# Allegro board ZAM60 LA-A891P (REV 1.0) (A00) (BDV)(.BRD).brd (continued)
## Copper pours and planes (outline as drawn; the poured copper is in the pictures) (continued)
GND on IN2 (solid shape): 11.19,11.92 11.19,11.45 10.69,10.96 9.66,10.96 9.52,11.1 9.52,11.81 9.76,12.05 11.06,12.05
GND on IN2 (solid shape): 17.78,13.86 17.78,12.86 17.6,12.69 16.6,12.69 16.35,12.93 16.35,13.76 16.55,13.96 17.68,13.96
GND on IN2 (solid shape): 16.43,18.26 16.43,17.02 16.18,16.78 15.1,16.78 14.91,16.97 14.91,18.24 15.02,18.35 16.33,18.35
GND on IN2 (solid shape): 52.14,15.46 52.14,12.05 51.88,11.79 47.43,11.79 47.1,12.12 47.1,15.48 47.54,15.92 51.68,15.92
GND on IN2 (solid shape): 17.3,15.89 17.3,14.81 17.13,14.64 16.09,14.64 15.61,15.13 15.61,15.85 15.94,16.18 17.02,16.18
GND on IN2 (solid shape): 103.12,57.51 103.12,47.21 102.79,46.88 100.4,46.88 100.26,47.01 100.26,57.44 100.58,57.76 102.87,57.76
GND on IN2 (solid shape): 295.11,70.46 295.37,70.02 295.85,69.84 300.25,69.84 300.25,69.85 301.15,69.85 301.32,69.77 301.4,69.6 301.4,63.45 301.32,63.28 301.15,63.2 300.25,63.2 300.25,63.21 296.5,63.21 296.5,63.2 292.46,63.2 291.62,63.69 291,62.95 291,61.76 287.78,61.76 287.33,62.2 287.33,62.9 287.72,63.28 287.72,64.3 291.27,67.86 291.27,69.63 291.59,69.95 294.07,69.95 294.58,70.46
GND on IN2 (solid shape): outline of 89 points within 70.81,70.97 77.85,81.13
GND on IN2 (solid shape): 233.25,109.24 233.75,109.05 233.99,108.57 234.02,108.34 235.59,108.34 235.59,98.3 235.62,98.09 235.71,97.9 235.71,96.75 235.26,96.3 231.57,96.3 230.69,97.18 230.69,100.81 230.25,101.26 226.5,101.26 225.87,100.62 225.87,98.21 225.23,97.57 222.06,97.57 221.68,97.95 221.68,101.19 222.35,101.19 223.41,100.99 223.21,102.05 223.21,108.29 224.94,108.29 224.96,108.54 225.19,109.04 225.7,109.24
GND on IN2 (solid shape): 253.09,107.5 257.35,103.24 261.61,107.5 261.61,108.62 263.89,108.62 263.89,100.56 263.5,100.23 263.4,99.73 261.56,99.73 260.22,101.07 257.36,101.07 255.65,99.35 255.65,97.19 255.08,96.62 250.38,96.62 250.01,96.99 250.01,108.34 251.58,108.34 251.61,108.57 251.85,109.05 252.34,109.24 253.09,109.24
GND on IN2 (solid shape): outline of 206 points within 283.79,78.69 303.15,94.03
GND on IN2 (solid shape): outline of 109 points within 0.25,0.25 304.5,50.58
GND on IN2 (solid shape): outline of 541 points within 33.97,27.99 77.49,109.25
GND on IN2 (solid shape): 100.54,100.85 107.7,93.69 114.86,100.85 114.86,107.74 125.7,107.74 126.59,108.11 127.03,109.17 127.2,109.24 177.7,109.24 177.87,109.17 178.31,108.11 179.2,107.74 188.54,107.74 188.54,100.85 195.7,93.69 202.86,100.85 202.86,109.24 204.7,109.24 205.21,109.04 205.44,108.54 205.46,108.29 207.19,108.29 207.19,102.05 206.99,100.99 208.05,101.19 208.79,101.19 208.79,97.95 208.4,97.57 202.62,97.57 194.02,93.38 188.04,100.85 188.04,102.95 187.58,103.42 183.7,103.42 182.24,104.88 182.24,106.67 181.67,107.24 179.2,107.24 178.05,107.67 177.46,108.74 127.44,108.74 126.85,107.67 125.7,107.24 121.61,107.24 121.16,106.78 121.16,104.81 119.76,103.42 115.88,103.42 115.36,102.89 115.36,100.85 108.91,93.28 100.42,98.46 95.12,98.46 93.34,96.68 92.2,96.68 91.91,96.98 91.91,108.34 93.48,108.34 93.51,108.57 93.75,109.05 94.24,109.24 100.54,109.24
GND on IN2 (solid shape): outline of 11195 points within 71.12,10.13 227.39,27.52
GND on IN3 (solid shape): 52.58,15.79 52.58,12.04 52.32,11.79 47.57,11.79 47.32,12.04 47.32,15.16 48.19,16.04 52.32,16.04
GND on IN3 (solid shape): 103.12,57.51 103.12,47.36 102.79,47.03 100.37,47.03 100.26,47.13 100.26,57.38 100.64,57.76 102.87,57.76
GND on IN3 (solid shape): 295.11,70.46 295.37,70.02 295.85,69.84 300.33,69.84 300.33,69.85 301.15,69.85 301.32,69.77 301.4,69.6 301.4,63.45 301.32,63.28 301.15,63.2 300.33,63.2 300.33,63.21 296.77,63.21 296.77,63.2 292.46,63.2 291.62,63.69 291,62.95 291,61.76 287.78,61.76 287.33,62.2 287.33,62.9 287.72,63.28 287.72,64.3 291.27,67.86 291.27,69.63 291.59,69.95 294.07,69.95 294.58,70.46
GND on IN3 (solid shape): outline of 89 points within 71.88,71.06 77.58,81.11
GND on IN3 (solid shape): 233.25,109.24 233.75,109.05 233.99,108.57 234.02,108.34 235.59,108.34 235.59,98.3 235.62,98.09 235.71,97.9 235.71,96.75 235.26,96.3 230.88,96.3 230.69,96.49 230.69,100.81 230.25,101.26 226.5,101.26 225.87,100.62 225.87,98.21 225.23,97.57 222.06,97.57 221.68,97.95 221.68,101.19 222.35,101.19 223.41,100.99 223.21,102.05 223.21,108.29 224.94,108.29 224.96,108.54 225.19,109.04 225.7,109.24
GND on IN3 (solid shape): 253.09,107.5 257.35,103.24 261.61,107.5 261.61,108.62 263.89,108.62 263.89,100.56 263.5,100.23 263.4,99.73 261.56,99.73 260.22,101.07 257.36,101.07 255.65,99.35 255.65,97.19 255.08,96.62 250.38,96.62 250.01,96.99 250.01,108.34 251.58,108.34 251.61,108.57 251.85,109.05 252.34,109.24 253.09,109.24
GND on IN3 (solid shape): outline of 206 points within 283.79,78.69 303.15,94.03
GND on IN3 (solid shape): outline of 542 points within 33.97,27.99 77.49,109.25
GND on IN3 (solid shape): 100.54,100.85 107.7,93.69 114.86,100.85 114.86,107.74 125.7,107.74 126.59,108.11 127.03,109.17 127.2,109.24 177.7,109.24 177.87,109.17 178.31,108.11 179.2,107.74 188.54,107.74 188.54,100.85 195.7,93.69 202.86,100.85 202.86,109.24 204.7,109.24 205.21,109.04 205.44,108.54 205.46,108.29 207.19,108.29 207.19,102.05 206.99,100.99 208.05,101.19 208.79,101.19 208.79,97.95 208.4,97.57 202.62,97.57 194.02,93.38 188.04,100.85 188.04,102.95 187.58,103.42 183.7,103.42 182.24,104.88 182.24,106.67 181.67,107.24 179.2,107.24 178.05,107.67 177.46,108.74 127.44,108.74 126.85,107.67 125.7,107.24 121.6,107.24 121.16,106.79 121.16,104.81 119.76,103.42 115.88,103.42 115.36,102.89 115.36,100.85 108.91,93.28 100.42,98.46 95.12,98.46 93.34,96.68 92.2,96.68 91.91,96.98 91.91,108.34 93.48,108.34 93.51,108.57 93.75,109.05 94.24,109.24 100.54,109.24
GND on IN3 (solid shape): outline of 11893 points within 0.25,0.25 304.5,51.6
GND on IN4 (solid shape): 52.58,15.79 52.58,12.04 52.32,11.79 47.48,11.79 47.29,11.98 47.29,14.71 48.63,16.04 52.32,16.04
GND on IN4 (solid shape): 75.79,74.78 75.79,71.64 75.54,71.39 74.13,71.39 73.94,71.58 73.94,74.69 74.15,74.9 75.66,74.9
GND on IN4 (solid shape): 103.69,57.57 103.69,52.17 103.38,51.85 100.58,51.85 100.26,52.17 100.26,57.25 101.03,58.01 103.25,58.01
GND on IN4 (solid shape): 295.11,70.46 295.37,70.02 295.85,69.84 299.55,69.84 299.55,69.85 301.15,69.85 301.32,69.77 301.4,69.6 301.4,63.45 301.32,63.28 301.15,63.2 299.55,63.2 299.55,63.21 296.41,63.21 296.41,63.2 292.46,63.2 291.62,63.69 291,62.95 291,61.76 287.78,61.76 287.33,62.2 287.33,62.9 287.72,63.28 287.72,64.3 291.27,67.86 291.27,69.63 291.59,69.95 294.07,69.95 294.58,70.46
GND on IN4 (solid shape): 233.25,109.24 233.75,109.05 233.99,108.57 234.02,108.34 235.59,108.34 235.59,98.3 235.62,98.09 235.71,97.9 235.71,96.94 235.39,96.62 234.69,96.62 233.17,98.15 230.88,98.15 230.69,98.34 230.69,100.81 230.25,101.26 226.5,101.26 225.87,100.62 225.87,98.34 225.61,98.08 223.2,98.08 222.69,97.57 222.06,97.57 221.68,97.95 221.68,101.19 222.35,101.19 223.41,100.99 223.21,102.05 223.21,108.29 224.94,108.29 224.96,108.54 225.19,109.04 225.7,109.24
GND on IN4 (solid shape): 253.09,107.5 257.35,103.24 261.61,107.5 261.61,108.62 263.89,108.62 263.89,100.56 263.5,100.23 263.4,99.73 261.56,99.73 260.22,101.07 257.36,101.07 255.65,99.35 255.65,97.19 255.08,96.62 250.38,96.62 250.01,96.99 250.01,108.34 251.58,108.34 251.61,108.57 251.85,109.05 252.34,109.24 253.09,109.24
GND on IN4 (solid shape): outline of 206 points within 283.79,78.69 303.15,94.03
GND on IN4 (solid shape): outline of 84 points within 33.97,27.99 77.49,109.25
GND on IN4 (solid shape): 100.54,100.85 107.7,93.69 114.86,100.85 114.86,107.74 125.7,107.74 126.59,108.11 127.03,109.17 127.2,109.24 177.7,109.24 177.87,109.17 178.31,108.11 179.2,107.74 188.54,107.74 188.54,100.85 195.7,93.69 202.86,100.85 202.86,109.24 204.7,109.24 205.21,109.04 205.44,108.54 205.46,108.29 207.19,108.29 207.19,102.05 206.99,100.99 208.05,101.19 208.79,101.19 208.79,97.95 208.4,97.57 202.62,97.57 194.02,93.38 188.04,100.85 188.04,102.95 187.58,103.42 183.7,103.42 182.24,104.88 182.24,106.65 181.66,107.24 179.2,107.24 178.05,107.67 177.46,108.74 127.44,108.74 126.85,107.67 125.7,107.24 121.61,107.24 121.16,106.78 121.16,104.81 119.76,103.42 115.88,103.42 115.36,102.89 115.36,100.85 108.91,93.28 100.42,98.46 95.12,98.46 94.04,97.38 94.04,88.68 93.98,88.62 90.48,88.62 90.48,89.83 92.39,91.73 92.39,96.53 92.2,96.72 92.17,96.72 91.91,96.98 91.91,108.34 93.48,108.34 93.51,108.57 93.75,109.05 94.24,109.24 100.54,109.24
GND on IN4 (solid shape): outline of 1654 points within 0.25,0.25 304.5,51.6
GND on IN4 (solid shape): outline of 2939 points within 117.52,55.54 154.56,70.08
GND on GND1: outline of 584 points within 0.25,0.25 304.5,109.25
GND on VCC: 65.26,79.44 65.16,79.6 63.93,81.28 62.61,82.89 62.6,83.01 62.7,83.06 63.06,83.26 62.99,83.66 62.96,83.73 62.99,83.8 62.74,84.4 62.48,83.8 62.51,83.73 62.48,83.66 62.41,83.55 62.38,83.42 62.31,83.33 62.2,83.36 58.79,86.67 54.96,89.49 54.12,89.87 53.2,90 50.27,90 50.27,100.58 51.5,100.58 53.1,101.25 53.77,102.85 53.77,108.23 71.3,108.23 71.36,108.17 71.36,85.42 65.38,79.44
GND on VCC: 176.56,9.32 175.17,10.71 143.97,10.71 142.7,9.44 113.09,9.44 113.09,47.16 119.53,47.16 120.19,47.82 120.19,53.6 121.5,54.91 124.87,54.91 128.93,58.97 134.44,58.97 135.07,58.34 159.2,58.34 160.32,57.22 160.32,53.66 164.14,49.78 164.14,48.38 165.12,47.41 168.74,47.41 170.01,46.14 177.5,46.14 178.14,45.5 190.71,45.5 191.34,44.87 198.39,44.87 222.44,20.89 222.42,10.69 221.05,9.32
GND on GND2: outline of 213 points within 0.25,0.25 304.5,109.25
GND on GND3: outline of 212 points within 0.25,0.25 304.5,109.25
GNDA on TOP (solid shape): 2.08,15.34 0.76,15.34 0.76,13.69 0.26,13.69 0.26,15.84 2.08,15.84
GNDA on TOP (solid shape): 1.44,28.49 33.46,28.49 33.46,27.99 1.4,27.99 1,27.99 0.83,27.92 0.76,27.75 0.76,24.66 1.44,24.66 1.44,24.15 0.25,24.15 0.25,27.75 0.47,28.28 1,28.5 1.44,28.5
GNDA on BOTTOM (solid shape): 2.08,15.34 0.76,15.34 0.76,13.69 0.26,13.69 0.26,15.84 2.08,15.84
GNDA on BOTTOM (solid shape): 1.31,28.49 33.46,28.49 33.46,27.99 0.99,27.99 0.83,27.92 0.76,27.76 0.76,24.66 1.63,24.66 1.63,24.16 0.26,24.16 0.26,27.55 0.25,27.55 0.25,27.75 0.47,28.28 1,28.5 1.31,28.5
GNDA on BOTTOM (solid shape): outline of 101 points within 25.65,15.6 30.41,21.69
GNDA on IN1 (solid shape): 2.08,15.34 0.76,15.34 0.76,13.69 0.26,13.69 0.26,15.84 2.08,15.84
GNDA on IN1 (solid shape): 1.3,28.49 33.46,28.49 33.46,27.99 0.99,27.99 0.83,27.92 0.76,27.76 0.76,24.66 1.63,24.66 1.63,24.16 0.26,24.16 0.26,27.45 0.25,27.45 0.25,27.75 0.47,28.28 1,28.5 1.3,28.5
GNDA on IN2 (solid shape): 2.08,15.34 0.76,15.34 0.76,13.69 0.26,13.69 0.26,15.84 2.08,15.84
GNDA on IN2 (solid shape): 1.25,28.49 33.46,28.49 33.46,27.99 0.99,27.99 0.83,27.92 0.76,27.76 0.76,24.66 1.63,24.66 1.63,24.16 0.26,24.16 0.26,27.48 0.25,27.48 0.25,27.75 0.47,28.28 1,28.5 1.25,28.5
GNDA on IN3 (solid shape): 2.08,15.34 0.76,15.34 0.76,13.69 0.26,13.69 0.26,15.84 2.08,15.84
GNDA on IN3 (solid shape): 1.31,28.49 33.46,28.49 33.46,27.99 0.99,27.99 0.83,27.92 0.76,27.76 0.76,24.66 1.63,24.66 1.63,24.16 0.26,24.16 0.26,27.55 0.25,27.55 0.25,27.75 0.47,28.28 1,28.5 1.31,28.5
GNDA on IN4 (solid shape): 2.08,15.34 0.76,15.34 0.76,13.69 0.26,13.69 0.26,15.84 2.08,15.84
GNDA on IN4 (solid shape): 1.31,28.49 33.46,28.49 33.46,27.99 0.99,27.99 0.83,27.92 0.76,27.76 0.76,24.66 1.63,24.66 1.63,24.16 0.26,24.16 0.26,27.55 0.25,27.55 0.25,27.75 0.47,28.28 1,28.5 1.31,28.5
GNDA on GND1: 27.98,10.96 26.33,12.61 10.14,12.61 9.06,13.69 0.26,13.69 0.26,15.84 12.45,15.84 13.19,16.47 12.71,17.31 12.71,22.69 13.19,23.53 12.45,24.15 0.26,24.15 0.26,27.47 0.25,27.47 0.25,27.75 0.47,28.28 1,28.5 1.31,28.5 1.31,28.49 33.46,28.49 33.46,22.49 33.02,22.05 33.02,20.27 32.91,20.17 31.07,20.17 30.67,19.76 30.67,15.36 31.07,14.96 32.15,14.96 32.19,14.92 32.19,13.6 31.62,13.03 31.62,12.53 31.11,12.02 31.11,11.19 30.88,10.96
GNDA on VCC: 27.98,10.96 26.33,12.61 10.14,12.61 9.06,13.69 1.27,13.69 1.27,14.83 12.45,14.83 14.08,15.91 13.72,17.83 13.72,22.17 14.08,24.09 12.45,25.17 1.27,25.17 1.27,27.48 33.46,27.48 33.46,22.49 33.02,22.05 33.02,20.27 32.91,20.17 31.07,20.17 30.67,19.76 30.67,15.36 31.07,14.96 32.15,14.96 32.19,14.92 32.19,13.6 31.62,13.03 31.62,12.53 31.11,12.02 31.11,11.19 30.88,10.96
GNDA on GND2: 27.98,10.96 26.33,12.61 10.14,12.61 9.06,13.69 0.26,13.69 0.26,15.84 12.45,15.84 13.19,16.47 12.71,17.31 12.71,22.69 13.19,23.53 12.45,24.15 0.26,24.15 0.26,27.09 0.25,27.09 0.25,27.75 0.47,28.28 1,28.5 1.43,28.5 1.43,28.49 33.46,28.49 33.46,22.49 33.02,22.05 33.02,20.27 32.91,20.17 31.07,20.17 30.67,19.76 30.67,15.36 31.07,14.96 32.15,14.96 32.19,14.92 32.19,13.6 31.62,13.03 31.62,12.53 31.11,12.02 31.11,11.19 30.88,10.96
GNDA on GND3: 27.98,10.96 26.33,12.61 10.14,12.61 9.06,13.69 0.26,13.69 0.26,15.84 12.45,15.84 13.19,16.47 12.71,17.31 12.71,22.69 13.19,23.53 12.45,24.15 0.26,24.15 0.26,27.27 0.25,27.27 0.25,27.75 0.47,28.28 1,28.5 1.08,28.49 33.46,28.49 33.46,22.49 33.02,22.05 33.02,20.27 32.91,20.17 31.07,20.17 30.67,19.76 30.67,15.36 31.07,14.96 32.15,14.96 32.19,14.92 32.19,13.6 31.62,13.03 31.62,12.53 31.11,12.02 31.11,11.19 30.88,10.96
GNDA_CHG on TOP (solid shape): 81.79,84.68 81.91,84.56 82.48,84.56 82.48,83.98 82.23,83.73 82.23,82.78 82.36,82.65 82.36,82.02 81.58,82.02 81.07,81.51 77.78,81.51 77.53,81.25 77.53,80.68 77.4,80.56 76.77,80.56 76.77,81.13 76.26,81.13 76.26,80.56 76.01,80.56 76.01,81.38 76.34,81.71 76.34,82.16 77.14,82.95 77.14,85.14 81.79,85.14
VDD_1.35V on BOTTOM (solid shape): 66.47,9.82 66.47,9.7 65.77,9 64.88,9 64.75,9.13 64.75,9.38 64.88,9.51 65.33,9.51 65.71,9.89 66.4,9.89
+BL_PWR_SRC on TOP (solid shape): 108.6,89.55 108.51,89.12 108.92,88.94 110.37,87.49 110.67,87.49 112.39,85.76 112.65,85.76 112.96,85.45 112.96,84.37 112.77,84.18 108.96,84.18 108.07,85.06 107.63,85.06 107.63,87.29 106.55,88.37 106.55,89.66 106.71,89.83 108.33,89.83
+BL_PWR_SRC on BOTTOM (solid shape): 108.09,90.87 108.09,89.6 108.33,89.36 108.33,89.03 108.2,88.9 106.74,88.9 106.61,89.03 106.61,89.36 106.82,89.56 106.82,90.87 106.89,90.94 108.01,90.94
+DC_IN on BOTTOM (solid shape): outline of 232 points within 62.89,93.33 69.05,106.45
+DC_IN_SS on TOP (solid shape): 60.82,99.99 60.82,96.18 64.4,92.61 64.4,90.72 63.98,90.29 59.33,90.29 58.67,90.95 58.67,94.37 57.21,95.83 57.21,99.86 57.53,100.18 60.63,100.18
+DC_IN_SS on BOTTOM (solid shape): 64.16,95 64.16,92.81 64.41,92.56 64.41,92.13 64.62,91.92 64.78,91.92 64.89,91.81 64.89,91.03 64.82,90.96 62.48,90.96 62.25,90.72 61.47,90.72 61.17,91.02 61.17,95.01 61.37,95.21 63.94,95.21
+DCIN on BOTTOM (solid shape): 77.79,88.91 77.79,88.08 77.47,87.76 77.47,85.23 78.01,84.68 78.01,84.35 77.91,84.25 77.2,84.25 76.64,84.81 73.39,84.81 73.02,85.18 73.02,87.07 73.33,87.38 74.74,87.38 75.03,87.67 75.21,87.67 75.43,87.89 75.43,88.07 76.37,89.01 77.7,89.01
+DCIN_JACK on TOP (solid shape): 59.82,102.39 59.82,100.7 59.58,100.46 57.54,100.46 56.94,99.85 56.94,95.7 56.35,95.11 52.69,95.11 52.54,95.26 52.54,97.87 52.75,98.08 54.54,98.08 55.23,98.77 55.23,101.19 56,101.96 58.05,101.96 58.57,102.47 59.74,102.47
+DCIN_JACK on BOTTOM (solid shape): 62.7,106.31 62.7,105.3 63.04,104.96 64.25,104.96 65.3,103.9 65.3,103.47 64.72,103.2 65.3,102.93 65.3,97.3 63.49,95.49 60.86,95.49 60.53,95.16 52.56,95.16 52.47,95.25 52.47,97.51 52.66,97.7 60.28,97.7 61.12,98.53 61.12,103.2 60.86,103.46 60.86,106 61.26,106.4 62.61,106.4
+DCIN_JACK on IN1 (solid shape): 62.57,99.94 62.57,95.41 62.25,95.1 52.84,95.1 52.5,95.44 52.5,99.1 53.52,100.11 62.39,100.11
+DCPRRTC on TOP (solid shape): outline of 155 points within 165.06,58.36 167.29,60.68
+DOCK_PWR_BAR on TOP (solid shape): outline of 164 points within 121.84,92.88 132.51,103.68
+DOCK_PWR_BAR on BOTTOM (solid shape): 100.31,80.94 100.31,78.53 100.12,78.34 96.76,78.34 96.63,78.47 96.63,80.94 96.82,81.13 100.12,81.13
+DOCK_PWR_BAR on BOTTOM (solid shape): outline of 247 points within 116,93.26 132.46,108.11
+DOCK_PWR_BAR on IN2 (solid shape): outline of 5482 points within 96.82,78.4 173.99,104.25
+EDP_VDD on TOP (solid shape): 117.63,90.05 117.63,89.19 117.87,88.94 117.87,88.33 117.8,88.25 116.13,88.25 116.01,88.37 116.01,90.14 116.2,90.33 117.35,90.33
+LCDVDD on TOP (solid shape): 115.82,90.14 115.82,89.45 115.25,89.45 115.25,88.94 115.82,88.94 115.82,88.47 115.64,88.29 113.27,88.29 113.1,88.45 113.1,88.8 113.09,88.81 113.09,91.29 113.28,91.48 114.49,91.48
+LCDVDD on BOTTOM (solid shape): 114.08,90.89 114.08,89.67 114.42,89.33 114.42,88.39 114.23,88.2 113.22,88.2 113.03,88.39 113.03,89.43 113.32,89.72 113.32,90.87 113.4,90.94 114.03,90.94
+LOM_VCT on BOTTOM (solid shape): 164.08,106.29 164.08,104.17 163.95,104.04 163.39,104.04 163.32,104.12 163.32,106.42 163.42,106.52 163.85,106.52
+PBATT on TOP (solid shape): 59.62,19.6 59.62,13.69 59.61,13.69 58.1,12.18 58.1,7.9 57.86,7.66 56.19,7.66 55.94,7.91 55.94,14.24 54.79,15.39 50.99,15.39 49.91,16.47 49.91,19.46 50.63,20.18 59.04,20.18
+PBATT on BOTTOM (solid shape): outline of 135 points within 88.96,65.13 99.07,74.51
+PBATT on IN2 (solid shape): 58.1,15.28 58.1,10.01 57.78,9.69 56.26,9.69 55.94,10.01 55.94,15.28 56.26,15.6 57.78,15.6
+PBATT on IN3 (solid shape): 57.85,13.11 57.85,9.87 57.67,9.69 56.19,9.69 55.94,9.94 55.94,12.99 56.19,13.25 57.71,13.25
+PBATT on IN4 (solid shape): 58.1,15.28 58.1,10.01 57.78,9.69 56.26,9.69 55.94,10.01 55.94,15.28 56.26,15.6 57.78,15.6
+PBATT on VCC: outline of 138 points within 49.34,16.67 90.23,77.51
+PCH_ASATA3PLL on TOP (solid shape): 164.02,80.24 164.02,78.71 163.89,78.59 162.43,78.59 162.18,78.84 162.18,80.3 163.95,80.3
+PCH_AUSB3PLL on TOP (solid shape): 161.6,79.48 161.41,79.48 159.06,77.13 158.49,77.13 158.37,77.25 158.37,78.14 159.83,79.6 159.83,80.3 161.6,80.3
+PCH_RTC_VCCSUS3_3 on TOP (solid shape): 164.39,57.83 164.38,57.8 164.37,57.68 164.4,57.56 164.4,57.55 164.4,57.17 164.39,57.15 164.34,57.11 164.29,57.15 163.6,57.02 164.29,56.9 164.34,56.94 164.39,56.91 164.4,56.88 164.4,56.68 164.21,56.49 162.96,56.49 162.94,56.51 162.94,57.19 163.07,57.31 163.32,57.31 163.51,57.51 163.51,57.82 163.64,57.95 164.27,57.95
+PCH_RTC_VCCSUS3_3 on IN2 (solid shape): 164.35,58 164.41,57.98 164.45,57.91 164.37,57.67 164.48,57.43 164.51,57.36 164.48,57.29 164.45,57.26 164.43,57.22 164.34,57.18 164.26,57.22 163.6,57.02 164.26,56.83 164.34,56.88 164.43,56.83 164.73,56.67 165.03,56.84 165.12,56.82 165.15,56.74 165.15,56.05 165.03,55.92 164.58,55.92 164.53,55.93 164.49,55.97 164.26,56.41 163.81,56.19 163.79,56.16 163.75,56.16 163.67,56.17 163.59,56.17 163.56,56.16 163.43,56.29 163.43,57.89 163.54,58
+PCH_VCCDSW3_3 on TOP (solid shape): 176.01,45.08 177.93,45.08 178.04,44.96 178.04,41.5 177.6,41.06 174.88,41.06 174.69,41.25 174.69,44.45 174.52,44.62 174.01,44.62 173.79,44.85 173.79,45.57 173.85,45.63 175.46,45.63
+PCH_VCCDSW3_3 on TOP (solid shape): 164.71,59.14 165.64,59.14 165.77,59 165.77,58.48 165.74,58.47 165.51,58.09 165.84,57.78 165.86,57.78 165.97,57.67 165.97,57.37 165.82,57.23 165.45,57.23 165.38,57.26 165.06,57.58 165.07,57.61 165.08,57.75 165.03,57.88 165.03,58.21 165.03,58.21 165.04,58.24 165.06,58.38 165.03,58.52 165.03,58.53 165.03,58.58 164.87,58.74 164.01,58.74 163.87,58.87 163.87,59.39 163.92,59.43 164.41,59.43
+PCH_VCCDSW3_3 on IN2 (solid shape): outline of 257 points within 165.41,55.73 170.81,57.82
+PWR_SRC on TOP (solid shape): 60.26,22.2 60.13,22.07 58.99,22.07 58.8,22.26 58.8,24.23 58.99,24.42 60.26,24.42
+PWR_SRC on TOP (solid shape): 113.66,83.54 113.55,83.26 113.66,82.97 113.66,81.32 113.22,80.87 111.57,80.87 111.44,81 111.44,83.6 111.57,83.73 113.47,83.73
+PWR_SRC on TOP (solid shape): 83.97,77.07 83.97,69.56 82.64,69.56 82.28,69.2 82.64,68.85 84.3,68.85 85.96,67.18 85.96,66.4 80.95,66.4 79.94,67.4 79.94,77.05 80.06,77.17 83.87,77.17
+PWR_SRC on BOTTOM (solid shape): 94.92,53.64 94.92,50.21 94.72,50.01 91.56,50.01 91.18,50.39 91.18,53.44 91.56,53.82 94.73,53.82
+PWR_SRC on BOTTOM (solid shape): 85.72,76.82 85.72,67.8 86.13,67.4 87.16,67.4 87.55,67 87.55,62.45 87.27,62.17 86.27,62.17 85.98,62.46 85.98,66.1 85.67,66.41 78.89,66.41 78.72,66.57 78.72,76.8 79.25,77.32 85.23,77.32
+PWR_SRC on BOTTOM (solid shape): 214.95,65.57 214.95,61.41 214.91,61.38 210.3,61.38 209.18,62.5 209.18,62.62 208.7,63.11 208.7,66.42 208.71,66.43 214.08,66.43
+PWR_SRC on IN2 (solid shape): 84.78,76.5 84.78,67.76 84.36,67.35 80.13,67.35 79.8,67.68 79.8,76.95 80.05,77.19 84.08,77.19
+PWR_SRC on VCC: 58.61,18.07 58.61,23.62 59.54,24.55 64.94,24.55 86.99,46.6 86.99,63.81 90.74,67.56 90.74,74.18 89.64,75.29 80.3,75.29 80.07,75.52 80.07,80.96 80.62,81.51 90.59,81.51 91.25,82.16 91.25,88.94 118.47,88.94 123.8,94.27 156.67,94.27 158.9,92.05 186.07,92.05 188.87,89.26 195.64,89.26 195.64,78.55 201.6,72.58 201.6,68.27 202.89,66.97 212.03,66.97 212.72,66.29 212.72,60.91 212.3,60.49 211.25,60.5 197.64,60.5 192.78,65.36 192.78,70.82 178.66,84.94 161.56,84.94 156.48,79.86 106.64,79.86 98.42,71.64 98.42,47.96 68.6,18.13 61.72,18.07
+PWR_SRC_AC on TOP (solid shape): 117.29,101.25 117.29,99.98 117.65,99.62 120.93,99.62 121.29,99.27 121.29,95.73 120.97,95.41 116.23,95.41 115.96,95.67 115.96,101.25 116.13,101.42 117.11,101.42
+PWR_SRC_AC on BOTTOM (solid shape): 119.43,101.01 119.43,99.29 119.82,98.89 119.82,97.57 119.5,97.26 116.13,97.26 115.81,97.57 115.81,99.83 115.86,100.34 115.87,100.85 115.87,101.07 115.93,101.14 119.3,101.14
+PWR_SRC_AC on BOTTOM (solid shape): 66.44,88.96 66.8,88.61 67.16,88.96 67.16,90.33 67.82,90.33 68.01,90.14 68.01,89.06 70.8,86.27 70.8,84.59 71.59,83.81 71.59,81.08 67.97,77.46 67.1,77.46 66.02,78.54 66.02,80.44 67.17,81.58 67.17,84.59 65.1,86.66 65.1,88.82 65.1,88.83 65.1,90.18 65.26,90.33 66.44,90.33
+PWR_SRC_AC on IN2 (solid shape): outline of 590 points within 68.07,85.38 119.82,99.42
+PWR_SRC_AC on IN3 (solid shape): outline of 590 points within 68.07,85.38 119.82,99.42
+RTC_CELL on TOP (solid shape): 162.63,59.45 162.79,59.45 162.79,59.42 162.91,59.3 162.91,58.69 163.01,58.58 164.78,58.58 164.91,58.46 164.91,58.27 164.78,58.14 163.57,58.14 163.32,57.89 163.32,57.57 163.19,57.44 162.81,57.44 162.62,57.63 162.62,57.75 162.49,57.87 162.47,57.96 162.52,58.04 162.67,58.5 162.21,58.68 162.11,58.69 162.07,58.77 162.07,59.4 162.13,59.46 162.63,59.46
+SD_IO_LDO on TOP (solid shape): 288.21,28.75 288.21,28.1 288.53,27.79 288.53,27.39 288.48,27.34 288.29,27.34 287.33,28.3 287.33,28.76 287.38,28.81 288.15,28.81
+SDC_IN on TOP (solid shape): 65.66,98.89 66.24,98.89 67.13,98.01 67.13,96.57 67.71,95.99 67.9,95.99 68.34,95.55 68.34,93.94 68.12,93.73 67.43,93.73 66.62,92.91 64.68,92.91 62.42,95.17 62.42,98.72 62.61,98.91 65.65,98.91
+SDC_IN on BOTTOM (solid shape): 69.72,95.22 69.72,92.94 69.53,92.75 68.27,92.75 67.97,92.44 67.97,91.35 67.18,91.35 67.18,93.13 66.42,93.13 66.42,91.35 66.37,91.3 65.94,91.3 65.85,91.39 65.85,93.6 66.44,94.2 66.44,95.36 66.6,95.52 69.43,95.52
+SM_VREF_CA on IN3 (solid shape): outline of 135 points within 140.33,52.67 142.38,54.92
+USB_LEFT_PWR on TOP (solid shape): 89.63,96.28 89.63,93.46 88.95,92.77 88.05,92.77 87.93,92.89 87.93,93.53 87.81,93.64 87.81,95.13 87.83,95.15 87.83,96.23 88.07,96.47 89.44,96.47
+USB_LEFT_PWR on BOTTOM (solid shape): 85.07,88.48 85.07,88.29 85.07,87.97 85.34,87.78 85.61,87.51 85.61,86.93 86.58,85.96 86.67,85.82 86.81,85.73 87.29,85.25 87.88,85.25 88.52,84.62 88.52,82.91 88.33,82.72 86.61,82.72 86.48,82.85 86.48,83.96 84.61,85.83 83.55,85.83 83.55,86.84 83.56,86.85 83.56,87.34 83.61,87.39 83.61,87.56 83.61,88.42 83.73,88.55 85,88.55
+USB_LEFT_PWR on IN3 (solid shape): 85.13,88.5 85.13,88.38 85.12,88.37 85.04,88.13 85.13,87.89 85.13,87.49 86.45,86.17 86.45,86.15 86.59,85.74 87,85.6 87.02,85.6 87.63,85 87.63,84.68 87.5,84.56 86.74,84.56 84.92,86.37 84.3,86.37 83.64,87.03 83.64,88.42 83.82,88.6 85.03,88.6
+USB_LEFT_PWR on IN4 (solid shape): outline of 155 points within 83.77,86.6 89.84,96.49
+USB_RIGHT_PWR on BOTTOM (solid shape): 251.57,93.45 251.57,92.13 251.57,92.12 251.55,91.99 251.57,91.85 251.57,91.85 251.57,91.48 251.48,91.39 249.82,91.39 249.36,90.94 249.36,90.78 248.09,90.78 247.71,91.16 247.71,91.92 246.76,92.87 246.76,93.7 245.74,94.72 245.74,96.11 246.06,96.43 248.59,96.43
+V_DDR_REF on BOTTOM (solid shape): 71.27,10.43 70.25,10.43 69.91,10.09 68.78,10.09 68.73,10.14 68.73,10.24 68.78,10.29 69.61,10.29 70.3,10.99 71.27,10.99
+VCHGR on TOP (solid shape): outline of 85 points within 85.01,63.42 91.74,77.16
+VCHGR on BOTTOM (solid shape): outline of 139 points within 85.93,63.48 92.87,77.62
+VCHGR on IN1 (solid shape): 91.7,77.06 91.7,74.54 91.13,73.96 89.14,73.96 88.68,73.51 88.68,67.69 88.26,67.27 85.25,67.27 85.11,67.41 85.11,75.02 87.24,75.02 87.24,74.97 87.25,74.91 87.27,74.86 87.29,74.81 87.32,74.77 87.36,74.73 87.4,74.7 87.45,74.67 87.49,74.65 87.55,74.64 87.6,74.64 87.65,74.64 87.71,74.65 87.75,74.67 87.8,74.7 87.84,74.73 87.88,74.77 87.91,74.81 87.93,74.86 87.95,74.91 87.96,74.97 87.96,75.02 87.95,75.07 87.93,75.12 87.91,75.17 87.88,75.22 87.84,75.25 87.8,75.29 87.75,75.31 87.71,75.33 87.65,75.35 87.6,75.35 87.55,75.35 87.49,75.33 87.45,75.31 87.4,75.29 87.36,75.25 87.32,75.22 87.29,75.17 87.27,75.12 87.25,75.07 87.24,75.02 85.11,75.02 85.11,76.12 86.26,77.27 91.5,77.27
+VCHGR on IN2 (solid shape): 91.7,77.02 91.7,74.38 91.32,74 89.14,74 88.77,73.63 88.77,67.31 88.54,67.08 85.68,67.08 85.47,67.3 85.47,75.02 87.24,75.02 87.24,74.97 87.25,74.91 87.27,74.86 87.29,74.81 87.32,74.77 87.36,74.73 87.4,74.7 87.45,74.67 87.49,74.65 87.55,74.64 87.6,74.64 87.65,74.64 87.71,74.65 87.75,74.67 87.8,74.7 87.84,74.73 87.88,74.77 87.91,74.81 87.93,74.86 87.95,74.91 87.96,74.97 87.96,75.02 87.95,75.07 87.93,75.12 87.91,75.17 87.88,75.22 87.84,75.25 87.8,75.29 87.75,75.31 87.71,75.33 87.65,75.35 87.6,75.35 87.55,75.35 87.49,75.33 87.45,75.31 87.4,75.29 87.36,75.25 87.32,75.22 87.29,75.17 87.27,75.12 87.25,75.07 87.24,75.02 85.47,75.02 85.47,76.45 86.13,77.11 91.62,77.11
+VHDMI_VCC on BOTTOM (solid shape): 227.7,98.95 227.7,97.99 226.9,97.19 226.79,97.19 226.01,96.41 224.22,96.41 223.87,96.06 219.96,96.06 218.82,97.19 218.82,98.91 219.01,99.1 219.71,99.1 220.02,98.78 220.02,97.89 220.66,97.26 223.97,97.26 224.41,97.69 225.61,97.69 226.35,98.42 226.35,99.03 226.6,99.29 227.35,99.29
+VLDOIN_1.35V on TOP (solid shape): 71.82,15.98 72.32,15.98 72.32,16.55 72.9,16.55 73.02,16.42 73.02,15.15 72.83,14.96 71.24,14.96 71.12,15.09 71.12,16.42 71.24,16.55 71.82,16.55
+VLDOIN_1.35V on BOTTOM (solid shape): 73.15,16.17 73.15,15.15 72.96,14.96 70.48,14.96 69.78,14.26 69.78,13.31 69.21,12.74 68.31,12.74 68.12,12.54 68.12,11.73 68.07,11.68 67.97,11.68 67.92,11.73 67.92,14.17 70.1,16.36 72.96,16.36
-DCIN_JACK on TOP (solid shape): 58.12,94.09 58.12,90.9 57.57,90.35 53.93,90.35 53.23,91.05 53.23,94.37 53.34,94.47 57.74,94.47
-DCIN_JACK on BOTTOM (solid shape): 60.57,94.47 60.57,91.92 58.94,90.3 53.73,90.3 53.02,91.01 53.02,94.58 53.15,94.7 60.33,94.7
BOOT_1.35V on BOTTOM (solid shape): 67.71,14.49 67.71,11.75 67.66,11.7 67.56,11.7 67.51,11.75 67.51,12.67 67.23,12.95 67.23,13.37 66.8,13.8 66.8,14.58 67.62,14.58
BOOT_1.35V_C on BOTTOM (solid shape): 67.62,15.34 65.53,15.34 65.53,15.98 67.62,15.98
BQ24770_REGN on BOTTOM (solid shape): 76.64,82.59 76.39,82.33 75.82,82.33 75.29,81.81 75.29,81.8 75.25,81.77 75.25,81.09 75.04,80.88 74.42,80.88 74.32,80.98 74.32,81.84 74.38,81.91 74.89,81.91 75.09,82.12 75.09,82.33 75.54,82.78 76.64,82.78
BST_3V on TOP (solid shape): 222.3,50.03 222.22,49.96 220.65,49.96 220.49,49.8 219.33,49.8 219.27,49.85 219.27,49.96 219.34,50.02 220.27,50.02 221.28,51.04 222.3,51.04
BST_5V on TOP (solid shape): 216.3,50.02 217.23,50.02 217.29,49.96 217.29,49.85 217.24,49.8 216.07,49.8 215.92,49.96 215.26,49.96 215.08,50.13 214.42,50.13 214.42,51.04 215.29,51.04
CHAGER_SRC on TOP (solid shape): 69.75,75.39 69.75,67.34 70.23,66.86 70.23,66.23 70.04,66.04 68.74,66.04 67.08,67.7 67.08,72.76 67.31,72.99 67.31,74.07 67.32,74.08 67.39,74.41 67.43,74.75 67.52,74.84 68.68,74.84 69.28,75.44 69.71,75.44
CHAGER_SRC on BOTTOM (solid shape): outline of 156 points within 67.13,66.05 75.31,80.77
CHG_BTS on BOTTOM (solid shape): 78.01,83.21 78.01,83.11 77.96,83.06 77.05,83.06 76.92,82.93 76.46,82.93 76.44,82.91 75.41,82.91 74.91,82.4 74.91,82.15 74.28,82.15 74.28,83.04 74.47,83.23 76.31,83.23 76.34,83.26 77.96,83.26
CHG_BTS_C on BOTTOM (solid shape): 73.56,84.27 73.56,82.19 73.52,82.15 72.88,82.15 72.85,82.19 72.85,84.27 72.88,84.31 73.52,84.31
CHG_LGATE on TOP (solid shape): 74.46,76.17 74.46,75.18 74.25,74.98 73.64,74.98 73.32,75.3 73.32,76.17 73.5,76.35 74.28,76.35
CHG_LGATE on BOTTOM (solid shape): 78.01,82.42 78.01,82.3 77.96,82.24 77.17,82.24 76.92,82 76.92,81.85 76.03,80.96 75.52,80.96 75.41,81.07 75.41,81.7 75.87,82.15 76.42,82.15 76.74,82.47 77.96,82.47
CHG_LGATE on IN4 (solid shape): 74.67,76.93 74.67,75.75 74.58,75.67 73.43,75.67 73.25,75.84 73.25,76.96 73.35,77.06 74.54,77.06
CHG_LGATE on IN4 (solid shape): 75.94,82.14 76.18,82.14 76.26,82.05 76.26,80.47 76.01,80.21 75.12,80.21 74.97,80.36 74.97,81.81 75.31,82.14 75.94,82.14
CHG_SNUB on TOP (solid shape): 74.61,78.66 74.61,78.07 74.41,77.86 73.51,77.86 73.3,77.66 73.3,76.54 73.21,76.45 72.16,76.45 72.1,76.52 72.1,78.29 72.6,78.8 74.47,78.8
CHG_SW on TOP (solid shape): 71.65,78.87 71.65,76.21 72.04,75.82 72.6,75.82 73.34,75.08 73.34,71.26 72.77,70.69 70.11,70.69 70.01,70.79 70.01,73.21 70.02,73.22 70.02,75.43 69.49,75.96 69.49,78.7 69.92,79.13 71.38,79.13
CHG_SW on BOTTOM (solid shape): 73.66,74.8 73.66,73.94 74.1,73.49 75.82,73.49 76.02,73.29 76.02,68.29 75.77,68.04 72.18,68.04 72.04,68.17 72.04,70.37 71.79,70.62 70.75,70.62 70.56,70.81 70.56,74.78 70.84,75.06 71.42,75.06 71.52,75.15 73.31,75.15
CHG_SW on BOTTOM (solid shape): 77.13,84.07 77.96,84.07 78.01,84.02 78.01,83.9 77.96,83.84 76.64,83.84 76.49,83.99 75.17,83.99 74.93,83.76 74.93,83.44 74.91,83.42 74.28,83.42 74.27,83.43 74.27,84.36 74.47,84.56 76.64,84.56
CHG_SW on IN4 (solid shape): 72.28,75.62 72.28,74.72 72.17,74.61 70.6,74.61 70.49,74.72 70.49,75.64 70.61,75.76 72.14,75.76
CHG_SW on IN4 (solid shape): 76.26,84.62 76.26,84.62 76.26,84.11 76.13,83.98 75.18,83.98 75.18,83.99 74.67,83.48 73.97,83.48 73.78,83.67 73.78,84.11 74.41,84.74 76.13,84.74
CHG_UGATE on TOP (solid shape): 68.95,76.64 68.95,75.52 68.4,74.98 67.9,74.98 67.76,75.11 67.76,76.06 68.48,76.77 68.82,76.77
CHG_UGATE on BOTTOM (solid shape): 76.57,83.72 77.1,83.72 77.15,83.67 77.96,83.67 78.01,83.62 78.01,83.51 77.96,83.46 77.15,83.46 77.1,83.41 76.31,83.41 76.26,83.36 75.23,83.36 75.1,83.48 75.1,83.74 75.23,83.87 76.42,83.87
CHG_UGATE on IN1 (solid shape): 69.78,76.94 69.78,75.67 69.56,75.46 68.53,75.46 68.27,75.72 68.27,76.83 68.51,77.07 69.65,77.07
CHG_UGATE on IN1 (solid shape): 76.25,83.74 76.25,83.27 76.01,83.03 75.5,83.03 75.24,82.78 74.51,82.78 74.29,82.99 74.29,83.73 74.43,83.87 76.12,83.87
CORE_BOOT on BOTTOM (solid shape): 99.54,58.19 99.54,57.53 99.77,57.3 100.61,57.3 100.66,57.25 100.66,57.14 100.61,57.09 99.41,57.09 99.13,57.37 99.13,57.6 98.85,57.88 98.35,57.88 98.35,58.41 98.37,58.44 99.29,58.44
CORE_BOOT_C on BOTTOM (solid shape): 97.96,57.89 97.52,57.45 97.52,56.62 96.88,56.62 96.88,57.51 97.46,58.08 97.46,58.4 97.96,58.4
CORE_BOOT_R on BOTTOM (solid shape): 98.92,57.35 99.3,56.97 99.67,56.97 99.74,56.89 100.58,56.89 100.63,56.84 100.63,56.75 100.57,56.69 98.98,56.69 98.92,56.62 98.28,56.62 98.28,57.51 98.92,57.51
CORE_SNUB on BOTTOM (solid shape): 104.76,49.58 101.96,49.58 101.84,49.7 101.84,50.4 102.85,50.4 103.04,50.59 104.76,50.59
CORE_SW on BOTTOM (solid shape): 104.44,56.37 107.1,56.37 107.27,56.19 107.27,55.61 107.3,55.59 107.3,55.36 109.65,53.01 109.65,50.78 107.3,50.78 107.3,49.89 109.65,49.89 109.65,48.37 109.39,48.11 105.46,48.11 105.14,48.43 105.14,50.72 104.82,51.04 103.55,51.04 103.04,51.54 103.04,53.39 103.3,53.64 103.3,53.67 105.43,53.67 105.44,53.61 105.45,53.56 105.47,53.51 105.5,53.46 105.53,53.41 105.57,53.38 105.61,53.34 105.66,53.32 105.72,53.3 105.77,53.29 105.83,53.29 105.88,53.29 105.94,53.31 105.99,53.33 106.04,53.36 106.08,53.39 106.12,53.44 106.15,53.48 106.17,53.53 106.19,53.59 106.19,53.64 106.19,53.7 106.19,53.75 106.17,53.81 106.15,53.86 106.12,53.9 106.08,53.94 106.04,53.98 105.99,54.01 105.94,54.03 105.88,54.05 105.83,54.05 105.77,54.05 105.72,54.04 105.66,54.02 105.61,54 105.57,53.96 105.53,53.92 105.5,53.88 105.47,53.83 105.45,53.78 105.44,53.73 105.43,53.67 103.3,53.67 103.3,56.5 104.31,56.5
DH_1.35V on TOP (solid shape): 67.62,14.07 67.62,13.63 67.31,13.31 67.31,13.12 67.05,12.86 66.8,12.86 66.23,13.44 66.23,13.63 67.05,14.45 67.24,14.45
DH_1.35V on TOP (solid shape): 69.91,22.4 69.91,20.75 69.77,20.61 68.64,20.61 68.64,21.37 68.45,21.56 68.45,22.39 68.58,22.52 69.8,22.52
DH_1.35V on BOTTOM (solid shape): 67.1,13.25 67.1,12.87 67.31,12.67 67.31,11.75 67.26,11.7 67.15,11.7 67.1,11.75 67.1,12.52 66.8,12.82 66.71,12.82 66.28,13.25 66.28,13.64 66.34,13.7 66.66,13.7
DL_1.35V on TOP (solid shape): 65.47,18.58 65.47,17.75 65.34,17.63 64.45,17.63 64.32,17.75 64.32,18.58 64.45,18.71 65.34,18.71
DL_1.35V on BOTTOM (solid shape): 66.47,11.62 66.47,11.35 66.4,11.28 65.71,11.28 65.63,11.36 65.63,11.62 65.55,11.86 65.33,11.98 65.14,12.18 65.14,12.45 65.25,12.56 65.52,12.56
DL_1.35V on IN4 (solid shape): 65.4,18.05 65.4,15.21 65.15,14.96 65.15,12.99 66.09,12.05 66.09,11.85 65.92,11.68 65.74,11.68 65.42,12 64.94,12 64.64,12.29 64.64,12.29 64.2,12.74 64.2,15.47 64.39,15.66 64.39,17.79 64.39,17.79 64.39,18.03 64.53,18.16 65.29,18.16
INT_SPK_L+ on BOTTOM (solid shape): 23.69,7.34 26.03,7.34 26.16,7.21 26.16,6.64 26.03,6.51 22.91,6.51 22.8,6.62 22.8,7.46 22.86,7.52 23.51,7.52
INT_SPK_L- on BOTTOM (solid shape): 25.4,9.15 25.4,8.4 25.3,8.3 22.9,8.3 22.82,8.38 22.82,9.19 22.86,9.22 25.32,9.22
INT_SPK_L- on IN4 (solid shape): 33.72,12.32 33.72,11.89 33.59,11.76 33.33,11.76 33.26,11.84 32.67,11.84 32.4,11.56 31.66,11.56 31.63,11.58 31.63,11.79 32.27,12.42 33.61,12.42
INT_SPK_R+ on BOTTOM (solid shape): 26.1,10.2 26.1,9.63 25.97,9.5 22.95,9.5 22.83,9.61 22.83,10.4 22.85,10.42 25.88,10.42
INT_SPK_R+ on IN3 (solid shape): 35.16,11.58 35.16,9.99 34.8,9.63 34.35,9.63 34.22,9.75 34.22,10.13 34.45,10.36 34.45,11.61 34.57,11.72 35.02,11.72
INT_SPK_R- on BOTTOM (solid shape): 25.33,12.04 25.33,11.47 25.21,11.34 22.92,11.34 22.86,11.4 22.86,12.1 22.92,12.17 25.21,12.17
INT_SPK_R- on IN3 (solid shape): 34.2,11.62 34.2,10.55 33.93,10.29 33.53,10.29 33.46,10.35 33.46,11.44 33.74,11.72 34.1,11.72
INT_SPKR_L+ on TOP (solid shape): 4.59,13.07 4.59,11.46 3.59,10.46 2.7,10.46 2.58,10.59 2.58,11.02 2.7,11.15 3.21,11.15 3.8,11.74 3.8,13.06 3.9,13.16 4.51,13.16
INT_SPKR_L+ on BOTTOM (solid shape): 3.36,10.96 3.36,8.42 3.11,8.17 2.47,8.17 2.22,8.42 2.22,10.96 2.41,11.15 3.17,11.15
INT_SPKR_L+ on BOTTOM (solid shape): 22.64,7.48 22.64,6.76 22.58,6.71 20.83,6.71 20.7,6.83 20.7,7.4 20.83,7.53 22.59,7.53
INT_SPKR_L- on TOP (solid shape): 5.84,13.06 5.84,10.7 5.59,10.45 4.63,10.45 4.51,10.58 4.51,10.9 4.63,11.02 4.89,11.02 5.05,11.19 5.05,13.06 5.14,13.16 5.74,13.16
INT_SPKR_L- on BOTTOM (solid shape): 5.33,10.96 5.33,8.36 5.14,8.17 4.51,8.17 4.25,8.42 4.25,10.96 4.44,11.15 5.14,11.15
INT_SPKR_L- on BOTTOM (solid shape): 22.63,9.16 22.63,8.4 22.58,8.36 20.83,8.36 20.7,8.48 20.7,9.05 20.83,9.18 22.6,9.18
INT_SPKR_R+ on TOP (solid shape): 7.1,13.06 7.1,11.38 7.24,11.24 7.24,10.64 7.05,10.45 6.6,10.45 6.31,10.74 6.31,13.08 6.39,13.16 7,13.16
INT_SPKR_R+ on BOTTOM (solid shape): 22.63,10.4 22.63,9.67 22.59,9.63 20.83,9.63 20.7,9.75 20.7,10.32 20.83,10.45 22.58,10.45
INT_SPKR_R+ on BOTTOM (solid shape): 7.36,10.96 7.36,8.42 7.11,8.17 6.47,8.17 6.28,8.36 6.28,10.96 6.47,11.15 7.17,11.15
INT_SPKR_R- on TOP (solid shape): 8.35,13.06 8.35,11.79 9.14,10.99 9.14,10.64 8.95,10.45 8.47,10.45 7.55,11.36 7.55,13.06 7.66,13.16 8.25,13.16
INT_SPKR_R- on BOTTOM (solid shape): 22.48,12.1 22.48,11.4 22.41,11.34 20.83,11.34 20.7,11.47 20.7,12.04 20.83,12.17 22.41,12.17
INT_SPKR_R- on BOTTOM (solid shape): 9.33,10.96 9.33,8.36 9.14,8.17 8.44,8.17 8.25,8.36 8.25,10.96 8.44,11.15 9.14,11.15
LG_3V on TOP (solid shape): 222.92,54.02 222.93,54.02 222.93,53.64 222.68,53.39 222.04,53.39 219.19,50.53 219.06,50.53 219,50.59 219,51.42 221.65,54.07 222.87,54.07
LG_5V on TOP (solid shape): 216.91,57 216.91,55.98 216.63,55.7 215.58,55.7 215.49,55.79 215.49,56.52 216.09,57.12 216.79,57.12
LG_5V on TOP (solid shape): 217.6,51.42 217.6,50.59 217.52,50.52 217.42,50.52 217.01,50.92 216.89,50.92 216.4,51.4 216.4,51.76 216.51,51.86 217.15,51.86
LG_5V on IN1 (solid shape): 216.98,56.93 216.98,56.17 216.85,56.04 216.53,56.04 216.39,55.9 216.39,55.48 215.38,55.48 215.38,56.5 216,57.12 216.79,57.12
LG_5V on IN1 (solid shape): 216.38,52.51 217.28,51.61 217.28,51.04 217.15,50.91 216.96,50.91 215.36,52.51 215.36,53.31 215.38,53.32 216.38,53.32
NB_PSID on TOP (solid shape): 60.69,103.21 60.69,102.76 60.59,102.65 59.4,102.65 59.31,102.74 59.31,103.21 59.64,103.54 60.36,103.54
NB_PSID on BOTTOM (solid shape): 60.71,103.09 60.71,102.52 60.53,102.34 60.36,102.34 60.26,102.35 60.16,102.34 60.12,102.32 59.99,102.23 59.91,102.08 59.91,101.91 59.99,101.76 60.01,101.69 59.99,101.63 60.09,101.08 60.6,101.31 60.68,101.38 60.77,101.35 60.89,101.23 60.89,98.95 60.12,98.17 53.17,98.17 53.09,98.25 53.09,99.32 55.86,102.09 58.27,102.09 59.46,103.29 60.51,103.29
Net_7 on BOTTOM (solid shape): 45.62,16.62 45.72,16.61 45.81,16.62 46.03,16.62 46.06,16.6 46.06,10.41 45.96,10.31 43.43,10.31 43.03,10.72 43.03,16.5 43.15,16.62
Net_8 on BOTTOM (solid shape): 64.86,16.28 64.86,11.81 64.79,11.75 64.4,11.75 64.36,11.71 64.36,10.43 64.32,10.39 61.85,10.39 61.8,10.44 61.8,11.81 62.39,11.81 62.39,11.76 62.4,11.71 62.42,11.65 62.44,11.61 62.47,11.56 62.51,11.52 62.55,11.49 62.59,11.46 62.64,11.44 62.69,11.43 62.75,11.43 62.8,11.43 62.85,11.44 62.9,11.46 62.95,11.49 62.99,11.52 63.03,11.56 63.06,11.61 63.08,11.65 63.1,11.71 63.1,11.76 63.1,11.81 63.1,11.86 63.08,11.92 63.06,11.96 63.03,12.01 62.99,12.05 62.95,12.08 62.9,12.11 62.85,12.13 62.8,12.14 62.75,12.14 62.69,12.14 62.64,12.13 62.59,12.11 62.55,12.08 62.51,12.05 62.47,12.01 62.44,11.96 62.42,11.92 62.4,11.86 62.39,11.81 61.8,11.81 61.8,16.66 61.83,16.7 64.44,16.7
PBAT_PRES#_C on BOTTOM (solid shape): 53.62,17.75 53.62,12.31 53.39,12.09 52.57,12.09 52.43,12.23 52.43,15.26 52.77,15.6 52.77,17.76 52.91,17.89 53.48,17.89
PBAT_SMBCLK_C on BOTTOM (solid shape): 56.63,17.87 56.63,15.53 56.37,15.27 55.95,15.27 55.77,15.45 55.77,17.85 55.89,17.97 56.54,17.97
PBAT_SMBDAT_C on BOTTOM (solid shape): 55.12,17.74 55.12,15.49 54.91,15.29 54.36,15.29 54.27,15.38 54.27,17.79 54.4,17.92 54.94,17.92
PBATT+_C on TOP (solid shape): 63.56,13.15 63.56,12.06 63.42,11.93 63.14,11.93 62.91,12.17 62.59,12.17 62.37,11.94 62.37,11.63 62.8,11.19 62.8,10.12 62.46,9.78 61.99,9.78 61.85,9.64 61.85,7.91 61.59,7.66 58.65,7.66 58.3,8 58.3,12.14 59.81,13.65 63.06,13.65
PBATT+_C on BOTTOM (solid shape): 61.5,17.7 61.5,9.09 61.27,8.86 58.32,8.86 58.02,9.16 58.02,12.97 57.22,13.78 57.22,14.82 57.3,14.82 57.3,14.76 57.31,14.71 57.33,14.66 57.36,14.61 57.4,14.57 57.44,14.53 57.48,14.49 57.53,14.47 57.58,14.45 57.64,14.44 57.69,14.44 57.75,14.44 57.8,14.46 57.86,14.48 57.9,14.51 57.95,14.55 57.98,14.59 58.01,14.63 58.04,14.68 58.05,14.74 58.06,14.79 58.06,14.85 58.05,14.9 58.04,14.96 58.01,15.01 57.98,15.05 57.95,15.1 57.9,15.13 57.86,15.16 57.8,15.18 57.75,15.2 57.69,15.2 57.64,15.2 57.58,15.19 57.53,15.17 57.48,15.15 57.44,15.11 57.4,15.08 57.36,15.03 57.33,14.98 57.31,14.93 57.3,14.88 57.3,14.82 57.22,14.82 57.22,17.58 57.53,17.89 61.3,17.89
PBATT+_C on IN3 (solid shape): 62.67,12.36 62.67,12.13 62.39,11.79 62.67,11.44 62.67,8.74 62.29,8.36 58.8,8.36 58.29,8.86 58.29,12.36 58.61,12.67 62.35,12.67
PBATT+_C on IN4 (solid shape): 62.67,12.36 62.67,12.13 62.39,11.79 62.67,11.44 62.67,8.74 62.29,8.36 58.49,8.36 58.3,8.55 58.3,12.22 58.76,12.67 62.35,12.67
REGCTL_PNP10 on TOP (solid shape): 251.34,86.78 252.03,86.78 252.33,86.47 252.33,86.08 252.61,85.8 253.09,85.8 253.18,85.71 254.11,85.71 254.17,85.64 254.17,85.53 254.12,85.48 252.19,85.48 251.71,85.95 250.38,85.95 250.25,86.08 250.25,86.76 250.37,86.88 251.24,86.88
REGCTL_PNP10 on BOTTOM (solid shape): 251.75,86.77 251.75,85.74 251.65,85.64 250.19,85.64 250.1,85.72 250.1,86.66 250.35,86.9 251.61,86.9
RING2 on TOP (solid shape): 29.18,18.69 30.6,18.69 30.65,18.64 30.65,18.51 30.6,18.46 29.1,18.46 28.89,18.25 27.25,18.25 27.16,18.34 27.16,19.14 27.28,19.25 27.28,19.9 27.33,19.95 27.92,19.95
RING2_R on TOP (solid shape): 28.23,17.89 28.23,17.12 28.08,16.97 27.47,16.97 26.79,16.29 26.12,16.29 25.99,16.42 25.99,18.02 26.06,18.08 28.04,18.08
RING2_R on TOP (solid shape): 18.41,14.96 18.41,14.2 18.29,14.07 17.26,14.07 16.92,13.73 14.86,13.73 14.65,13.95 14.29,13.95 14.15,14.1 14.15,14.63 14.41,14.9 17,14.9 17.26,15.15 18.22,15.15
RING2_R on IN2 (solid shape): 4.7,15.47 4.7,14.83 5.08,14.45 14.28,14.45 14.73,14.9 15.5,14.9 15.66,14.74 15.66,13.87 15.48,13.69 3.11,13.69 2.79,14.01 2.79,15.4 3.11,15.72 4.44,15.72
RING2_R on IN3 (solid shape): 19.3,14.26 18.73,14.26 18.54,14.07 17.46,14.07 17.27,14.26 17.27,15.28 17.52,15.53 19.3,15.53
RING2_R on IN3 (solid shape): 27.11,17.39 27.11,16.18 26.22,15.29 25.59,15.29 25.21,15.67 25.21,16.5 26.29,17.58 26.92,17.58
RING2_R on IN3 (solid shape): 4.7,15.47 4.7,14.83 5.08,14.45 14.28,14.45 14.73,14.9 15.81,14.9 16,14.71 16,13.88 15.81,13.69 3.11,13.69 2.79,14.01 2.79,15.4 3.11,15.72 4.44,15.72
SLEEVE_R on TOP (solid shape): 16.44,25.37 16.44,19.44 16.74,19.15 17.45,19.15 17.85,18.74 19.64,18.74 19.92,19.02 23.27,19.02 23.58,18.71 23.58,18.25 23.72,18.11 25.52,18.11 25.61,18.02 25.61,17.26 25.21,16.85 23.6,16.85 23.2,17.25 23.2,17.25 23.12,17.37 23.01,17.45 23,17.45 22.57,17.88 21.88,17.88 21.7,17.7 17.5,17.7 17.03,18.17 15.45,18.17 14.98,18.64 14.98,24.55 13.84,25.69 4.38,25.69 4.06,25.37 4.06,24.61 2.28,24.61 2.28,26.33 2.92,26.96 14.86,26.96
SNB_1.05V on TOP (solid shape): 202.04,56.43 201.79,56.18 200.77,56.18 200.77,57.83 201.41,58.47 201.41,59.1 202.04,59.1
SNUB_1.35V on TOP (solid shape): 65.4,15.51 65.26,15.37 63.23,15.37 63.12,15.48 63.12,16.93 63.24,17.06 64.01,17.06 64.39,17.44 65.4,17.44
SNUB_3V on TOP (solid shape): 228.03,57.63 228.03,55.92 226.37,55.92 226.37,57.82 226.57,58.01 227.64,58.01
SNUB_5V on TOP (solid shape): 210.99,54.91 210.8,54.72 209.53,54.72 209.34,54.91 209.34,56.81 210.99,56.81
SW1 on TOP (solid shape): 216.05,49.63 217.24,49.63 217.29,49.58 217.29,49.45 217.24,49.4 216.19,49.4 215.66,48.86 214.42,48.86 214.42,49.78 215.9,49.78
SW1 on TOP (solid shape): 213.6,59.74 213.6,58.21 213.53,58.15 212.58,58.15 212.26,57.83 212.26,56.37 212.52,56.12 214.8,56.12 214.87,56.05 214.87,53.77 214.8,53.7 211.57,53.7 211.26,54.01 211.26,57.88 211.06,58.08 209.53,58.08 209.34,58.27 209.34,59.61 209.6,59.86 213.47,59.86
SW1 on BOTTOM (solid shape): 216.21,58.97 216.21,54.65 215.91,54.34 211.44,54.34 211.26,54.52 211.26,57.39 212.26,57.39 212.26,56.81 212.39,56.69 213.47,56.69 213.6,56.81 213.6,57.39 213.47,57.51 212.39,57.51 212.26,57.39 211.26,57.39 211.26,59.69 211.44,59.86 215.33,59.86
SW1 on IN1 (solid shape): 212.47,54.65 212.47,54.46 212.34,54.33 212.34,53.57 211.33,53.57 211.33,53.95 211.26,54.01 211.26,54.65 211.45,54.84 212.28,54.84
SW1 on IN1 (solid shape): 215.69,49.89 215.88,49.89 216.07,49.7 216.07,49.32 215.57,48.81 215.31,48.81 214.61,49.51 214.61,50.08 214.8,50.27 215.31,50.27
SW2 on TOP (solid shape): 226.11,58.97 226.11,54.9 226.74,54.27 228.03,54.27 228.03,53.25 223.9,53.25 223.58,53.57 223.58,53.76 223.57,53.77 223.57,56.75 223.31,57 223.31,59.04 223.44,59.16 225.92,59.16
SW2 on TOP (solid shape): 222.32,49.75 222.32,48.89 222.3,48.86 221.27,48.86 221.22,48.81 220.96,48.81 220.38,49.4 219.33,49.4 219.27,49.45 219.27,49.58 219.33,49.63 220.52,49.63 220.67,49.78 222.3,49.78
SW2 on BOTTOM (solid shape): 225.41,58.72 225.41,54.32 224.98,53.89 221.54,53.89 221.17,54.27 221.17,58.46 221.68,58.97 225.16,58.97
SW2 on IN1 (solid shape): 225.03,54.34 225.03,53.19 224.01,53.19 224.01,54.34 224.14,54.46 224.9,54.46
SW2 on IN1 (solid shape): 222.25,50.2 222.25,49.82 221.23,48.81 220.72,48.81 220.47,49.06 220.47,49.76 220.72,50.01 221.04,50.01 221.55,50.52 221.93,50.52
SW_1.35V on TOP (solid shape): 68.2,22.45 68.2,21.25 68.45,20.99 68.45,16.23 66.1,13.88 66.1,13.31 66.61,12.8 66.61,12.36 66.48,12.23 66.16,12.23 65.21,13.18 65.21,14.83 66.04,15.66 66.04,22.39 66.23,22.58 68.07,22.58
SW_1.35V on BOTTOM (solid shape): 68.13,21.82 68.13,17.82 67.82,17.5 66.35,17.5 65.47,18.39 64.07,18.39 63.75,18.71 63.75,22.26 67.69,22.26
SW_1.35V on BOTTOM (solid shape): 66.42,13.94 66.3,13.94 66.08,13.72 66.08,13.2 66.71,12.57 66.85,12.57 66.9,12.52 66.9,11.75 66.85,11.7 66.77,11.7 65.46,13.02 65.46,13.37 65.34,13.49 65.34,14.45 65.47,14.58 66.42,14.58
SW_+V1.05SP on TOP (solid shape): 204.52,60.12 204.52,55.61 204.39,55.48 203.44,55.48 203.31,55.61 203.31,60.31 204.33,60.31
SW_+V1.05SP on BOTTOM (solid shape): 204.3,60.52 204.3,59.36 205.03,58.63 205.03,55.67 204.76,55.41 201.61,55.41 201.29,55.73 201.29,58.39 201.67,58.78 202.29,58.78 202.61,59.1 202.8,59.1 203.12,59.42 203.12,60.56 204.26,60.56
UG_3V on TOP (solid shape): 221.03,51.29 221.03,51.04 220.2,50.21 219.33,50.21 219.27,50.26 219.27,50.36 219.38,50.46 219.63,50.46 220.58,51.42 220.9,51.42
UG_3V on TOP (solid shape): 225.54,59.8 225.54,59.54 225.41,59.42 223.44,59.42 223.31,59.54 223.31,59.86 223.44,59.99 225.35,59.99
UG_3V on IN1 (solid shape): 221.93,51.85 221.93,51.41 221.04,50.52 220.28,50.52 220.09,50.71 220.09,50.96 221.36,52.23 221.55,52.23
UG_3V on IN1 (solid shape): 225.54,59.89 225.54,59.23 225.41,59.1 224.58,59.1 224.2,58.72 223.63,58.72 223.5,58.85 223.5,59.48 224.04,60.02 225.41,60.02
UG_5V on TOP (solid shape): 213.61,57.79 213.61,56.94 213.53,56.87 212.52,56.87 212.44,56.94 212.44,57.63 212.7,57.88 213.52,57.88
UG_5V on TOP (solid shape): 216.93,50.45 217.2,50.45 217.29,50.36 217.29,50.26 217.24,50.21 216.35,50.21 215.62,50.95 215.62,51.33 215.69,51.4 215.97,51.4
UG_5V on IN1 (solid shape): 216.52,50.85 216.52,50.59 216.39,50.46 215.44,50.46 214.68,51.23 214.68,51.61 214.93,51.86 215.5,51.86
UG_5V on IN1 (solid shape): 213.74,57.12 213.74,55.98 212.79,55.98 212.72,56.04 212.72,56.49 212.4,56.81 212.4,57.19 212.6,57.38 213.48,57.38
N20364112 on TOP (solid shape): 31.95,14.9 31.95,13.81 30.96,12.83 30.39,12.83 30.31,12.9 30.31,13.21 30.41,13.31 31.04,13.31 31.75,14.02 31.75,14.9 31.8,14.96 31.9,14.96
N20813052 on BOTTOM (solid shape): 96.06,80.12 96.06,77.77 96.22,77.61 97.51,77.61 97.72,77.39 97.72,76 97.58,75.85 93.77,75.85 93.34,76.28 93.34,79.76 93.36,79.84 93.35,79.92 93.35,79.95 93.65,80.25 95.93,80.25
N20826302 on TOP (solid shape): 64.53,10.13 64.53,9.38 64.45,9.31 63.83,9.31 63.38,8.86 62.46,8.86 62.38,8.94 62.38,9.59 62.43,9.64 62.6,9.64 63.15,10.2 64.46,10.2
N20826302 on BOTTOM (solid shape): 66.49,10.23 66.49,10.13 66.44,10.08 65.63,10.08 65.25,9.7 63.11,9.7 62.99,9.82 62.99,10.08 63.12,10.21 64.67,10.21 64.82,10.17 64.97,10.21 65.12,10.21 65.2,10.28 66.44,10.28
N61500909 on TOP (solid shape): 105.71,70.71 104.85,69.84 104.85,68.68 104.8,68.63 104.7,68.63 104.64,68.68 104.64,70.39 104.19,70.85 103.55,70.85 103.55,71.48 105.71,71.48

Small or netless copper shapes (teardrops, artwork), in the pictures only: 43 on TOP, 311 on BOTTOM, 1 on IN4

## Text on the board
Ref Des/Silkscreen Bottom: DIMM A | DDR3L | LOW VOLTAGE | DIMM B | H22 | H19 | H20 | BT | WIGIG | WLAN | HCA | WWAN
User.Comments: LA-A891P | Lily_tang | 2014-07-16 | 2015-07-16 | ZAM60
Ref Des/Silkscreen Top: 1 | 2 | 3 | 4
USER_PART_NUM_BOTTOM: FIGURE | SIZE | 8.0 | 10.0 | 20.0 | 24.0 | 28.0 | 35.0 | 39.0 | 55.0 | 91.0 | 126.0 | 130.0 | 138.0 | 142.0 | 40.0 | 43.0 | 63.0 | 102.0 | 217.0 | 39.0x33.0 | 45.0x37.0 | 55.0x24.0 | 55.0x28.0 | 63.0x28.0 | 67.0x28.0 | 67.0x31.0 | 71.0x31.0 | 75.0x37.0 | 94.0x28.0 | 100.0x31.0 | 102.0x31.0 | 112.0x39.0 | 118.0x33.0 | 67.0x43.0 | 205.0x102.0 | DRILL CHART: TOP to BOTTOM | ALL UNITS ARE IN MILS | TOLERANCE | +3.0/-3.0 | +2.0/-2.0 | PLATED | NON-PLATED | QTY | 4660 | 515 | 19 | 10 | 27 | 7 | 2 | 11 | 1 | 4 | 9
